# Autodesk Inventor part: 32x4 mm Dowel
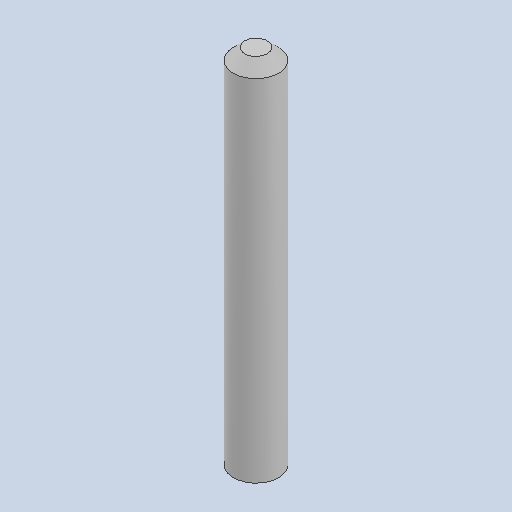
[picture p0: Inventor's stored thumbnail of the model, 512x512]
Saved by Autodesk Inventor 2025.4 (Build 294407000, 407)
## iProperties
Created: 2026-09
Part Number: 32x4 mm Dowel
Material: Generic
Document SubType Name: Modeling
Designer: AdminForWorker
Density: 1 g/cm^3
Appearance: Default
Title: 32x4 mm Dowel v1
Author: AdminForWorker
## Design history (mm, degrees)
feature "Body1"
body "Solid1"
